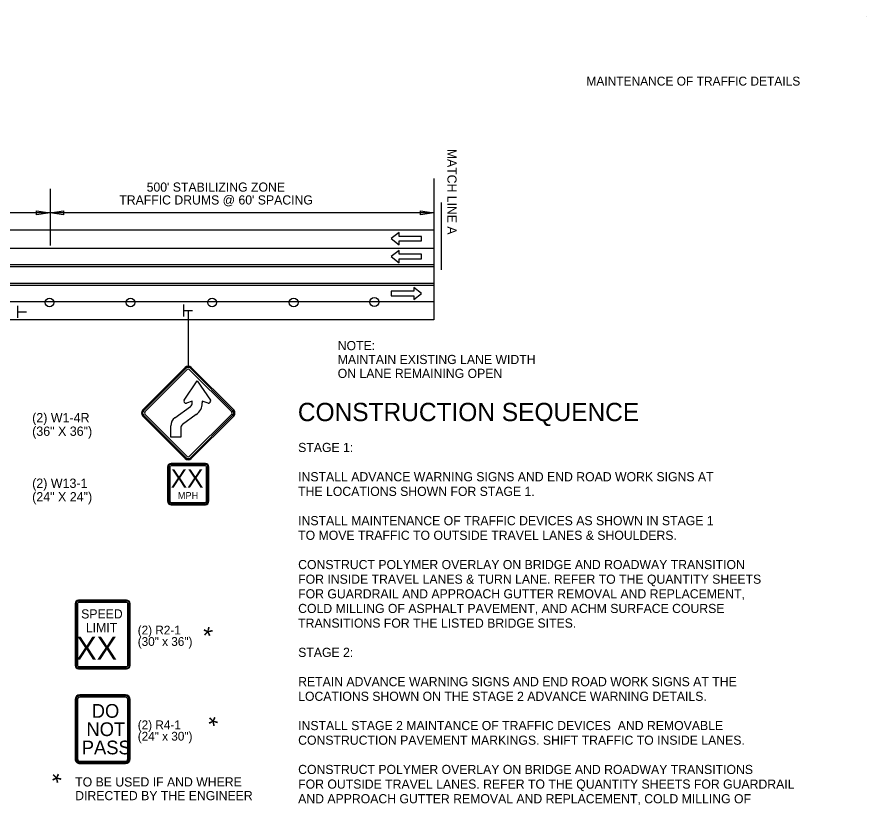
# Model space of a CAD drawing. Extents: x 1930579 to 1937984, y 596452 to 597630.
# Drawn here: x 1937427 to 1937984, y 597113 to 597630 of the extents above; entities that cross this region are included whole.
import ezdxf

# ---------------------------------------------------------------- set-up
doc = ezdxf.new("R2010")
doc.units = 0
for name, color, linetype in [('Default', 7, 'Continuous'), ('P_TC_Signs_Permanent', 7, 'Continuous'), ('R_Annotation', 7, 'Continuous'), ('R_Border', 7, 'Continuous'), ('R_Striping', 7, 'Continuous')]:
    doc.layers.add(name, color=color, linetype=linetype)

msp = doc.modelspace()

# ---------------------------------------------------------------- linework, layer by layer
at = {"layer": 'Default'}
for p, q in [((1937700.06, 597523.93), (1937700.06, 597431.19)), ((1937448.32, 597517.31), (1937448.32, 597480.01)), ((1937439.45, 597500.1), (1937439.45, 597502.76)), ((1937439.45, 597502.76), (1937448.32, 597501.43)), ((1937448.32, 597501.43), (1937457.19, 597502.76)), ((1937457.19, 597502.76), (1937457.19, 597500.1)), ((1937691.19, 597500.1), (1937691.19, 597502.76)), ((1937691.19, 597502.76), (1937700.06, 597501.43)), ((1937704.72, 597508.25), (1937704.72, 597464.19)), ((1937448.32, 597501.43), (1937081.1, 597501.43)), ((1937448.32, 597501.43), (1937439.45, 597500.1)), ((1937700.06, 597501.43), (1937448.32, 597501.43)), ((1937457.19, 597500.1), (1937448.32, 597501.43)), ((1937700.06, 597501.43), (1937691.19, 597500.1)), ((1937700.06, 597490.19), (1936671.76, 597490.19)), ((1937700.06, 597478.19), (1936493.11, 597478.19)), ((1937700.06, 597467.4), (1936671.76, 597467.4)), ((1937700.06, 597466.02), (1936671.76, 597466.02)), ((1937700.06, 597455.23), (1936671.76, 597455.23)), ((1937700.06, 597453.85), (1936671.76, 597453.85)), ((1937700.06, 597443.19), (1936493.11, 597443.19)), ((1937427.33, 597432.53), (1937427.33, 597440.51)), ((1937427.45, 597436.5), (1937432.89, 597436.5)), ((1937536.12, 597433.42), (1937536.12, 597441.4)), ((1937536.23, 597437.39), (1937541.68, 597437.39)), ((1937700.06, 597431.19), (1936671.76, 597431.19))]:
    msp.add_line(p, q, dxfattribs=at)
for centre in [(1937448.03, 597442.71), (1937501.12, 597442.71), (1937554.59, 597442.71), (1937608.06, 597442.71), (1937660.96, 597442.98)]:
    msp.add_circle(centre, 2.87, dxfattribs=at)
at = {"layer": 'P_TC_Signs_Permanent'}
for p, q in [((1937509.13, 597372.17), (1937536.97, 597400.02)), ((1937509.66, 597371.64), (1937537.5, 597399.49)), ((1937538.29, 597398.69), (1937510.45, 597370.85)), ((1937567.46, 597370.85), (1937539.62, 597398.69)), ((1937540.42, 597399.49), (1937568.26, 597371.64)), ((1937540.95, 597400.02), (1937568.79, 597372.17)), ((1937510.45, 597369.52), (1937538.29, 597341.68)), ((1937530.2, 597367.11), (1937540.41, 597374.47)), ((1937544.25, 597369.14), (1937535.2, 597362.62)), ((1937539.62, 597341.68), (1937567.46, 597369.52)), ((1937536.97, 597340.35), (1937509.13, 597368.2)), ((1937537.5, 597340.88), (1937509.66, 597368.73)), ((1937568.26, 597368.73), (1937540.42, 597340.88)), ((1937568.79, 597368.2), (1937540.95, 597340.35)), ((1937550.21, 597337.06), (1937527.71, 597337.06)), ((1937550.21, 597336.49), (1937527.71, 597336.49)), ((1937550.21, 597335.56), (1937527.71, 597335.56)), ((1937525.46, 597334.81), (1937525.46, 597312.31)), ((1937526.02, 597334.81), (1937526.02, 597312.31)), ((1937526.96, 597334.81), (1937526.96, 597312.31)), ((1937550.96, 597312.31), (1937550.96, 597334.81)), ((1937551.9, 597312.31), (1937551.9, 597334.81)), ((1937552.46, 597312.31), (1937552.46, 597334.81)), ((1937527.71, 597311.56), (1937550.21, 597311.56)), ((1937527.71, 597310.62), (1937550.21, 597310.62)), ((1937527.71, 597310.06), (1937550.21, 597310.06)), ((1937498.58, 597247.43), (1937467.08, 597247.42)), ((1937498.58, 597246.86), (1937467.08, 597246.86)), ((1937464.83, 597245.17), (1937464.83, 597204.67)), ((1937465.39, 597245.17), (1937465.39, 597204.67)), ((1937466.33, 597245.17), (1937466.33, 597204.67)), ((1937498.58, 597245.93), (1937467.08, 597245.92)), ((1937499.33, 597204.68), (1937499.33, 597245.18)), ((1937500.27, 597204.68), (1937500.27, 597245.18)), ((1937500.83, 597204.68), (1937500.83, 597245.18)), ((1937467.08, 597203.92), (1937498.58, 597203.93)), ((1937467.08, 597202.99), (1937498.58, 597202.99)), ((1937467.08, 597202.42), (1937498.58, 597202.43)), ((1937497.84, 597185.29), (1937467.84, 597185.29)), ((1937464.84, 597182.29), (1937464.84, 597143.29)), ((1937465.44, 597182.29), (1937465.44, 597143.29)), ((1937466.34, 597182.29), (1937466.34, 597143.29)), ((1937497.84, 597184.69), (1937467.84, 597184.69)), ((1937497.84, 597183.79), (1937467.84, 597183.79)), ((1937499.34, 597143.29), (1937499.34, 597182.29)), ((1937500.24, 597143.29), (1937500.24, 597182.29)), ((1937500.84, 597143.29), (1937500.84, 597182.29)), ((1937467.84, 597141.79), (1937497.84, 597141.79)), ((1937467.84, 597140.89), (1937497.84, 597140.89)), ((1937467.84, 597140.29), (1937497.84, 597140.29))]:
    msp.add_line(p, q, dxfattribs=at)
for points in [[(1937536.28, 597378.71), (1937544.86, 597391.28), (1937553.45, 597378.71)], [(1937541.58, 597376.75), (1937541.58, 597377.94), (1937537.77, 597376.72)], [(1937551.96, 597376.72), (1937548.15, 597377.94), (1937548.15, 597376.75)], [(1937534.04, 597360.34), (1937534.04, 597354.25), (1937527.47, 597354.25), (1937527.47, 597361.78)]]:
    msp.add_lwpolyline(points, dxfattribs=at)
for centre, radius, start, end in [((1937538.96, 597398.03), 2.81, 45, 135), ((1937538.96, 597398.03), 2.06, 45, 135), ((1937538.96, 597398.03), 0.937, 45, 135), ((1937537.36, 597377.97), 1.31, 145.6763, 287.8128), ((1937538.77, 597376.75), 2.81, 305.7733, 0), ((1937538.77, 597376.75), 9.38, 305.7733, 0), ((1937552.36, 597377.97), 1.31, 252.1872, 34.3237), ((1937511.12, 597370.18), 2.81, 135, 225), ((1937511.12, 597370.18), 2.06, 135, 225), ((1937511.12, 597370.18), 0.938, 135, 225), ((1937566.8, 597370.18), 0.937, 315, 45), ((1937566.8, 597370.18), 2.06, 315, 45), ((1937566.8, 597370.18), 2.81, 315, 45), ((1937534.04, 597361.78), 6.56, 125.7733, 180), ((1937536.85, 597360.34), 2.81, 125.7733, 180), ((1937538.96, 597342.34), 0.937, 225, 315), ((1937527.71, 597334.81), 2.25, 90, 180), ((1937527.71, 597334.81), 1.69, 90, 180), ((1937527.71, 597334.81), 0.75, 90, 180), ((1937538.96, 597342.34), 2.81, 225, 315), ((1937538.96, 597342.34), 2.06, 225, 315), ((1937550.21, 597334.81), 2.25, 360, 90), ((1937550.21, 597334.81), 1.69, 360, 90), ((1937550.21, 597334.81), 0.75, 360, 90), ((1937527.71, 597312.31), 2.25, 180, 270), ((1937527.71, 597312.31), 1.69, 180, 270), ((1937527.71, 597312.31), 0.75, 180, 270), ((1937550.21, 597312.31), 2.25, 270, 360), ((1937550.21, 597312.31), 1.69, 270, 360), ((1937550.21, 597312.31), 0.75, 270, 360), ((1937467.08, 597245.17), 2.25, 90.003, 180.003), ((1937467.08, 597245.17), 1.69, 90.003, 180.003), ((1937498.58, 597245.18), 2.25, 0.003, 90.003), ((1937498.58, 597245.18), 1.69, 0.003, 90.003), ((1937467.08, 597245.17), 0.75, 90.003, 180.003), ((1937498.58, 597245.18), 0.75, 0.003, 90.003), ((1937467.08, 597204.67), 2.25, 180.003, 270.003), ((1937467.08, 597204.67), 1.69, 180.003, 270.003), ((1937467.08, 597204.67), 0.75, 180.003, 270.003), ((1937498.58, 597204.68), 2.25, 270.003, 0.003), ((1937498.58, 597204.68), 1.69, 270.003, 0.003), ((1937498.58, 597204.68), 0.75, 270.003, 0.003), ((1937467.84, 597182.29), 3, 90.003, 180.003), ((1937497.84, 597182.29), 3, 0.003, 90.003), ((1937467.84, 597182.29), 2.4, 90.003, 180.003), ((1937467.84, 597182.29), 1.5, 90.003, 180.003), ((1937497.84, 597182.29), 2.4, 0.003, 90.003), ((1937497.84, 597182.29), 1.5, 0.003, 90.003), ((1937467.84, 597143.29), 3, 180.003, 270.003), ((1937467.84, 597143.29), 2.4, 180.003, 270.003), ((1937467.84, 597143.29), 1.5, 180.003, 270.003), ((1937497.84, 597143.29), 3, 270.003, 0.003), ((1937497.84, 597143.29), 2.4, 270.003, 0.003), ((1937497.84, 597143.29), 1.5, 270.003, 0.003)]:
    msp.add_arc(centre, radius, start, end, dxfattribs=at)
at = {"layer": 'R_Annotation'}
msp.add_line((1937538.96, 597437.39), (1937538.96, 597400.84), dxfattribs=at)
at = {"layer": 'R_Border'}
msp.add_line((1937984, 597629.92), (1937984, 597629.92), dxfattribs=at)
at = {"layer": 'R_Striping'}
for points in [[(1937677.28, 597488.56), (1937672.09, 597484.56), (1937677.28, 597480.56), (1937677.28, 597483.06), (1937691.99, 597483.06), (1937691.99, 597486.06), (1937677.28, 597486.06)], [(1937677.28, 597476.78), (1937672.09, 597472.78), (1937677.28, 597468.78), (1937677.28, 597471.28), (1937691.99, 597471.28), (1937691.99, 597474.28), (1937677.28, 597474.28)], [(1937686.8, 597444.61), (1937691.99, 597448.61), (1937686.8, 597452.61), (1937686.8, 597450.11), (1937672.09, 597450.11), (1937672.09, 597447.11), (1937686.8, 597447.11)]]:
    msp.add_lwpolyline(points, close=True, dxfattribs=at)

# ---------------------------------------------------------------- texts
at = {"layer": 'Default'}
for s, height, rotation, p in [('MATCH LINE A', 5.9996, 270, (1937708.87, 597543.42)), ("500' STABILIZING ZONE", 6, 360, (1937511.69, 597515.36)), ("TRAFFIC DRUMS @ 60' SPACING", 6, 360, (1937493.76, 597506.93))]:
    msp.add_text(s, height=height, rotation=rotation, dxfattribs=at).set_placement(p)
at = {"layer": 'P_TC_Signs_Permanent'}
for s, height, rotation, p in [('XX', 12, 360, (1937527.49, 597321.31)), ('MPH', 4.5, 360, (1937532.13, 597313.81)), ('SPEED', 6, 0.003, (1937468.76, 597235.42)), ('LIMIT', 6, 0.003, (1937471.85, 597226.42)), ('XX', 15, 0.003, (1937465.53, 597208.42)), ('DO', 9, 0.003, (1937475.67, 597170.29)), ('NOT', 9, 359.9626, (1937472.19, 597158.3)), ('PASS', 9, 0.003, (1937469.14, 597146.29))]:
    msp.add_text(s, height=height, rotation=rotation, dxfattribs=at).set_placement(p)
at = {"layer": 'R_Annotation'}
for s, height, rotation, p in [('NOTE:', 6, 360, (1937636.96, 597411.4)), ('MAINTAIN EXISTING LANE WIDTH', 6, 360, (1937636.96, 597402.29)), ('ON LANE REMAINING OPEN', 6, 360, (1937636.96, 597393.18)), ('CONSTRUCTION SEQUENCE', 12, 360, (1937610.84, 597364.85)), ('(2) W1-4R', 6.099, 360, (1937436.63, 597364.09)), ('(36" X 36")', 6.0988, 360, (1937436.63, 597355.21)), ('STAGE 1:', 6, 360, (1937611.03, 597344.59)), ('INSTALL ADVANCE WARNING SIGNS AND END ROAD WORK SIGNS AT', 6, 360, (1937611.03, 597325.39)), ('(2) W13-1', 6.099, 360, (1937436.63, 597321.07)), ('THE LOCATIONS SHOWN FOR STAGE 1.', 6, 360, (1937611.03, 597315.79)), ('(24" X 24")', 6.0988, 360, (1937436.63, 597312.19)), ('INSTALL MAINTENANCE OF TRAFFIC DEVICES AS SHOWN IN STAGE 1', 6, 360, (1937611.03, 597296.59)), ('TO MOVE TRAFFIC TO OUTSIDE TRAVEL LANES & SHOULDERS.', 6, 360, (1937611.03, 597286.99)), ('CONSTRUCT POLYMER OVERLAY ON BRIDGE AND ROADWAY TRANSITION', 6, 360, (1937611.03, 597267.79)), ('FOR INSIDE TRAVEL LANES & TURN LANE. REFER TO THE QUANTITY SHEETS ', 6, 360, (1937611.03, 597258.19)), ('FOR GUARDRAIL AND APPROACH GUTTER REMOVAL AND REPLACEMENT, ', 6, 360, (1937611.03, 597248.59)), ('COLD MILLING OF ASPHALT PAVEMENT, AND ACHM SURFACE COURSE ', 6, 360, (1937611.03, 597238.99)), ('TRANSITIONS FOR THE LISTED BRIDGE SITES.', 6, 360, (1937611.03, 597229.39)), ('(2) R2-1', 5.76, 0.003, (1937505.83, 597224.93)), ('*', 12, 135.003, (1937560.29, 597230.78)), ('(30" x 36")', 5.76, 0.003, (1937505.83, 597217.44)), ('STAGE 2:', 6, 360, (1937611.03, 597210.19)), ('RETAIN ADVANCE WARNING SIGNS AND END ROAD WORK SIGNS AT THE', 6, 360, (1937611.03, 597190.99)), ('LOCATIONS SHOWN ON THE STAGE 2 ADVANCE WARNING DETAILS.', 6, 360, (1937611.03, 597181.39)), ('(2) R4-1', 5.76, 0.003, (1937505.84, 597162.79)), ('*', 12, 45, (1937559.25, 597159.51)), ('INSTALL STAGE 2 MAINTANCE OF TRAFFIC DEVICES  AND REMOVABLE', 6, 360, (1937611.03, 597162.19)), ('(24" x 30")', 5.76, 0.003, (1937505.84, 597155.3)), ('CONSTRUCTION PAVEMENT MARKINGS. SHIFT TRAFFIC TO INSIDE LANES.', 6, 360, (1937611.03, 597152.59)), ('CONSTRUCT POLYMER OVERLAY ON BRIDGE AND ROADWAY TRANSITIONS', 6, 360, (1937611.03, 597133.39)), ('*', 12, 45, (1937456.66, 597122.28)), ('TO BE USED IF AND WHERE', 6, 360, (1937464.84, 597125.22)), ('FOR OUTSIDE TRAVEL LANES. REFER TO THE QUANTITY SHEETS FOR GUARDRAIL ', 6, 360, (1937611.03, 597123.79)), ('DIRECTED BY THE ENGINEER', 6, 360, (1937464.84, 597116.22)), ('AND APPROACH GUTTER REMOVAL AND REPLACEMENT, COLD MILLING OF ', 6, 360, (1937611.03, 597114.19))]:
    msp.add_text(s, height=height, rotation=rotation, dxfattribs=at).set_placement(p)
at = {"layer": 'R_Border'}
msp.add_text('MAINTENANCE OF TRAFFIC DETAILS', height=5.862, rotation=360, dxfattribs=at).set_placement((1937800, 597584.94))

doc.saveas('drawing.dxf')
